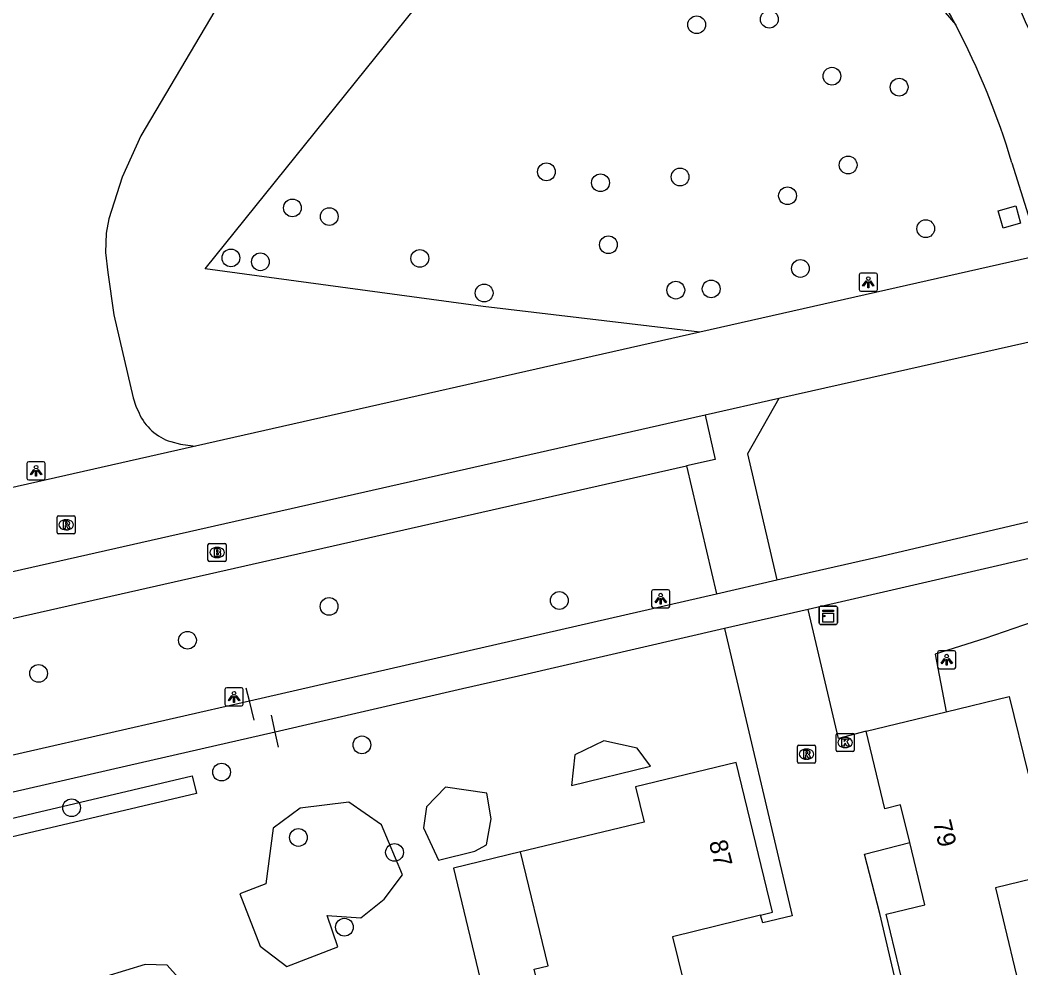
# Model space of a CAD drawing. Extents: x 156664 to 157568, y 383571 to 384421.
# Drawn here: x 156904.7 to 156959.8, y 384078.5 to 384130.7 of the extents above; entities that cross this region are included whole.
import ezdxf

# ---------------------------------------------------------------- set-up
doc = ezdxf.new("R2010")
doc.units = 0
for name, color, linetype in [('IMGEO_Boom', 7, 'Continuous'), ('IMGEO_Brandkraan', 7, 'Continuous'), ('IMGEO_Fietspad_gesloten', 7, 'Continuous'), ('IMGEO_Groenvoorziening', 7, 'Continuous'), ('IMGEO_Haag', 7, 'Continuous'), ('IMGEO_Hek', 7, 'Continuous'), ('IMGEO_Kast', 7, 'Continuous'), ('IMGEO_Kolk', 7, 'Continuous'), ('IMGEO_Lichtpunt', 7, 'Continuous'), ('IMGEO_Muur', 7, 'Continuous'), ('IMGEO_Naaldbos', 7, 'Continuous'), ('IMGEO_Pand', 7, 'Continuous'), ('IMGEO_Pand_nummerreeks', 7, 'Continuous'), ('IMGEO_Parkeervlak_open', 7, 'Continuous'), ('IMGEO_Rijbaan_lokaal_open', 7, 'Continuous'), ('IMGEO_Rioolput', 7, 'Continuous'), ('IMGEO_Voetpad_open', 7, 'Continuous')]:
    doc.layers.add(name, color=color, linetype=linetype)

msp = doc.modelspace()

# ---------------------------------------------------------------- linework, layer by layer
at = {"layer": 'IMGEO_Boom'}
for centre in [(156945.945, 384130.737), (156941.942, 384130.43), (156949.395, 384127.597), (156953.096, 384126.993), (156950.286, 384122.704), (156933.666, 384122.329), (156941.029, 384122.045), (156936.647, 384121.727), (156946.949, 384121.011), (156919.677, 384120.341), (156921.708, 384119.863), (156954.56, 384119.196), (156937.082, 384118.311), (156916.287, 384117.587), (156926.695, 384117.561), (156917.912, 384117.371), (156947.656, 384117.004), (156940.795, 384115.811), (156942.743, 384115.877), (156930.237, 384115.653), (156934.38, 384098.711), (156921.698, 384098.385), (156913.896, 384096.519), (156905.696, 384094.696), (156923.503, 384090.758), (156915.776, 384089.259), (156907.514, 384087.295), (156920.007, 384085.655), (156925.302, 384084.834), (156922.54, 384080.713)]:
    msp.add_circle(centre, 0.489, dxfattribs=at)
at = {"layer": 'IMGEO_Brandkraan'}
for p, q in [((156915.026, 384100.931), (156915.026, 384101.783)), ((156915.101, 384101.857), (156915.953, 384101.857)), ((156915.514, 384101.637), (156915.539, 384101.637)), ((156916.027, 384101.783), (156916.027, 384100.931)), ((156915.953, 384100.857), (156915.101, 384100.857)), ((156915.537, 384101.077), (156915.512, 384101.077))]:
    msp.add_line(p, q, dxfattribs=at)
for points in [[(156915.026, 384100.931), (156915.026, 384101.783)], [(156915.101, 384101.857), (156915.953, 384101.857)], [(156915.374, 384101.557), (156915.374, 384101.157), (156915.587, 384101.157)], [(156915.605, 384101.557), (156915.374, 384101.557)], [(156915.553, 384101.476), (156915.499, 384101.476), (156915.499, 384101.4)], [(156915.499, 384101.4), (156915.552, 384101.4)], [(156916.027, 384101.783), (156916.027, 384100.931)], [(156915.953, 384100.857), (156915.101, 384100.857)], [(156915.561, 384101.324), (156915.499, 384101.324), (156915.499, 384101.243)], [(156915.499, 384101.243), (156915.561, 384101.243)]]:
    msp.add_lwpolyline(points, dxfattribs=at)
for centre, radius, start, end in [((156915.103, 384101.781), 0.0765, 91.552, 178.448), ((156915.103, 384101.781), 0.0765, 91.552, 178.448), ((156915.554, 384101.438), 0.0379, 267.8285, 90.9355), ((156915.609, 384101.412), 0.145, 59.4692, 91.5367), ((156915.634, 384101.459), 0.0922, 285.5137, 58.1501), ((156915.951, 384101.781), 0.0765, 1.552, 88.448), ((156915.951, 384101.781), 0.0765, 1.552, 88.448), ((156915.103, 384100.933), 0.0765, 181.552, 268.448), ((156915.103, 384100.933), 0.0765, 181.552, 268.448), ((156915.562, 384101.283), 0.0404, 269.8759, 90.5077), ((156915.593, 384101.408), 0.251, 268.6676, 293.5347), ((156915.639, 384101.267), 0.105, 301.3115, 78.989), ((156915.951, 384100.933), 0.0765, 271.552, 358.448), ((156915.951, 384100.933), 0.0765, 271.552, 358.448)]:
    msp.add_arc(centre, radius, start, end, dxfattribs=at)
for centre, major_axis, ratio, start_param, end_param in [((156915.513, 384101.357), (-0.387, 0.002), 0.722429, 4.712389, 7.853982), ((156915.538, 384101.357), (-0.39, 0.002), 0.717154, 1.570796, 4.712389)]:
    msp.add_ellipse(centre, major_axis=major_axis, ratio=ratio, start_param=start_param, end_param=end_param, dxfattribs=at)
at = {"layer": 'IMGEO_Fietspad_gesloten'}
msp.add_lwpolyline([(156959.31, 384122.816), (156960.908, 384117.741)], dxfattribs=at)
for centre, radius, start, end in [((156917.342, 384110.12), 43.854, 27.5828, 32.8398), ((156914.405, 384109.729), 50.202, 20.2028, 27.9619), ((156917.613, 384110.277), 43.542, 16.7371, 27.565)]:
    msp.add_arc(centre, radius, start, end, dxfattribs=at)
at = {"layer": 'IMGEO_Groenvoorziening'}
for points in [[(156913.042, 384150.679), (156916.959, 384149.844), (156920.928, 384148.664), (156920.951, 384146.515), (156920.715, 384143.965), (156920.467, 384142.161), (156919.737, 384139.785), (156918.56, 384137.15), (156917.618, 384135.197), (156916.768, 384133.516), (156911.324, 384124.31), (156910.294, 384122.041), (156909.558, 384119.746), (156909.426, 384118.952), (156909.382, 384117.878), (156909.514, 384116.775), (156909.839, 384114.445), (156910.897, 384109.877), (156911.053, 384109.423), (156911.232, 384109.029)], [(156912.976, 384107.464), (156913.505, 384107.329), (156913.922, 384107.261), (156914.342, 384107.209)], [(156961.933, 384089.137), (156964.473, 384089.553), (156965.654, 384090.933), (156964.974, 384094.222), (156963.845, 384095.831), (156960.473, 384097.538), (156957.816, 384096.624), (156955.086, 384095.746), (156955.693, 384092.586)], [(156935.058, 384088.516), (156939.404, 384089.584), (156938.662, 384090.585), (156936.837, 384090.989), (156935.235, 384090.2), (156935.058, 384088.516)], [(156930.372, 384085.253), (156930.622, 384086.679), (156930.38, 384088.099), (156928.116, 384088.422), (156927.054, 384087.341), (156926.896, 384086.189), (156927.724, 384084.412), (156929.73, 384084.91), (156930.372, 384085.253)], [(156925.732, 384083.598), (156924.578, 384086.345), (156922.792, 384087.607), (156920.106, 384087.274), (156918.621, 384086.161), (156918.221, 384083.101), (156916.788, 384082.543), (156917.896, 384079.671), (156919.367, 384078.544), (156922.177, 384079.63), (156921.588, 384081.357), (156923.445, 384081.229), (156924.736, 384082.258), (156925.732, 384083.598)], [(156932.249, 384084.864), (156928.555, 384083.965), (156930.939, 384074.036)], [(156909.039, 384076.974), (156910.731, 384068.042), (156912.048, 384068.041), (156913.46, 384068.754), (156914.948, 384074.472), (156914.591, 384076.577), (156912.77, 384078.626), (156911.571, 384078.659), (156909.402, 384078), (156909.039, 384076.974)]]:
    msp.add_lwpolyline(points, dxfattribs=at)
msp.add_arc((156913.836, 384110.177), 2.846, 203.7829, 252.4099, dxfattribs=at)
at = {"layer": 'IMGEO_Haag'}
msp.add_lwpolyline([(156911.133, 384087.316), (156894.424, 384083.379), (156894.195, 384084.352), (156910.882, 384088.284), (156914.157, 384089.056), (156914.386, 384088.082), (156911.133, 384087.316)], dxfattribs=at)
at = {"layer": 'IMGEO_Hek'}
for points in [[(156917.305, 384093.191), (156917.132, 384093.888)], [(156917.57, 384092.125), (156917.305, 384093.191)], [(156918.727, 384091.464), (156918.524, 384092.403)], [(156918.907, 384090.628), (156918.727, 384091.464)]]:
    msp.add_lwpolyline(points, dxfattribs=at)
at = {"layer": 'IMGEO_Kast'}
for p, q in [((156948.694, 384097.468), (156948.694, 384098.309)), ((156948.694, 384098.309), (156948.694, 384097.468)), ((156948.769, 384098.393), (156949.61, 384098.393)), ((156949.61, 384098.393), (156948.769, 384098.393)), ((156949.694, 384098.318), (156949.694, 384097.477)), ((156949.694, 384097.477), (156949.694, 384098.318)), ((156949.619, 384097.393), (156948.778, 384097.393)), ((156948.778, 384097.393), (156949.619, 384097.393))]:
    msp.add_line(p, q, dxfattribs=at)
for points in [[(156948.889, 384098.183), (156949.489, 384098.183), (156949.489, 384098.098), (156948.889, 384098.098), (156948.889, 384098.183)], [(156948.889, 384098.008), (156949.489, 384098.008), (156949.489, 384097.519), (156948.889, 384097.519), (156948.889, 384098.008)]]:
    msp.add_lwpolyline(points, dxfattribs=at)
msp.add_circle((156948.973, 384097.857), 0.0377, dxfattribs=at)
for centre, start, end in [((156948.772, 384098.315), 92.4484, 184.2845), ((156948.772, 384098.315), 92.4484, 184.2845), ((156949.616, 384098.315), 2.4484, 94.2845), ((156949.616, 384098.315), 2.4484, 94.2845), ((156948.772, 384097.471), 182.4484, 274.2845), ((156948.772, 384097.471), 182.4484, 274.2845), ((156949.616, 384097.471), 272.4484, 4.2845), ((156949.616, 384097.471), 272.4484, 4.2845)]:
    msp.add_arc(centre, 0.0779, start, end, dxfattribs=at)
at = {"layer": 'IMGEO_Kolk'}
for p, q in [((156949.621, 384090.461), (156949.621, 384091.313)), ((156949.696, 384091.387), (156950.548, 384091.387)), ((156950.109, 384091.167), (156950.134, 384091.167)), ((156950.622, 384091.313), (156950.622, 384090.461)), ((156950.548, 384090.387), (156949.696, 384090.387)), ((156950.132, 384090.607), (156950.107, 384090.607))]:
    msp.add_line(p, q, dxfattribs=at)
for points in [[(156949.621, 384090.461), (156949.621, 384091.313)], [(156949.696, 384091.387), (156950.548, 384091.387)], [(156949.942, 384091.087), (156950.065, 384091.087), (156950.065, 384090.936), (156950.195, 384091.087), (156950.359, 384091.087), (156950.213, 384090.936), (156950.366, 384090.687), (156950.214, 384090.687), (156950.129, 384090.851), (156950.065, 384090.784), (156950.065, 384090.687), (156949.942, 384090.687), (156949.942, 384091.087)], [(156950.622, 384091.313), (156950.622, 384090.461)], [(156950.548, 384090.387), (156949.696, 384090.387)]]:
    msp.add_lwpolyline(points, dxfattribs=at)
for centre, start, end in [((156949.698, 384091.311), 91.552, 178.448), ((156949.698, 384091.311), 91.552, 178.448), ((156950.546, 384091.311), 1.552, 88.448), ((156950.546, 384091.311), 1.552, 88.448), ((156949.698, 384090.463), 181.552, 268.448), ((156949.698, 384090.463), 181.552, 268.448), ((156950.546, 384090.463), 271.552, 358.448), ((156950.546, 384090.463), 271.552, 358.448)]:
    msp.add_arc(centre, 0.0765, start, end, dxfattribs=at)
for centre, major_axis, ratio, start_param, end_param in [((156950.108, 384090.887), (-0.387, 0.002), 0.722429, 4.712389, 7.853982), ((156950.133, 384090.887), (-0.39, 0.002), 0.717154, 1.570796, 4.712389)]:
    msp.add_ellipse(centre, major_axis=major_axis, ratio=ratio, start_param=start_param, end_param=end_param, dxfattribs=at)
at = {"layer": 'IMGEO_Lichtpunt'}
for p, q in [((156950.9, 384116.652), (156950.9, 384115.845)), ((156950.9, 384116.652), (156950.9, 384115.845)), ((156951.802, 384116.747), (156950.994, 384116.747)), ((156951.802, 384116.747), (156950.994, 384116.747)), ((156951.896, 384115.845), (156951.896, 384116.652)), ((156951.896, 384115.845), (156951.896, 384116.652)), ((156950.994, 384115.751), (156951.802, 384115.751)), ((156950.994, 384115.751), (156951.802, 384115.751)), ((156905.057, 384106.26), (156905.057, 384105.453)), ((156905.057, 384106.26), (156905.057, 384105.453)), ((156905.959, 384106.355), (156905.151, 384106.355)), ((156905.959, 384106.355), (156905.151, 384106.355)), ((156906.053, 384105.453), (156906.053, 384106.26)), ((156906.053, 384105.453), (156906.053, 384106.26)), ((156905.151, 384105.359), (156905.959, 384105.359)), ((156905.151, 384105.359), (156905.959, 384105.359)), ((156939.464, 384099.212), (156939.464, 384098.405)), ((156939.464, 384099.212), (156939.464, 384098.405)), ((156940.366, 384099.307), (156939.558, 384099.307)), ((156940.366, 384099.307), (156939.558, 384099.307)), ((156940.46, 384098.405), (156940.46, 384099.212)), ((156940.46, 384098.405), (156940.46, 384099.212)), ((156939.558, 384098.311), (156940.366, 384098.311)), ((156939.558, 384098.311), (156940.366, 384098.311)), ((156956.119, 384095.945), (156955.311, 384095.945)), ((156956.119, 384095.945), (156955.311, 384095.945)), ((156955.217, 384095.85), (156955.217, 384095.043)), ((156955.217, 384095.85), (156955.217, 384095.043)), ((156956.213, 384095.043), (156956.213, 384095.85)), ((156956.213, 384095.043), (156956.213, 384095.85)), ((156955.311, 384094.949), (156956.119, 384094.949)), ((156955.311, 384094.949), (156956.119, 384094.949)), ((156915.963, 384093.806), (156915.963, 384092.999)), ((156915.963, 384093.806), (156915.963, 384092.999)), ((156916.865, 384093.901), (156916.057, 384093.901)), ((156916.865, 384093.901), (156916.057, 384093.901)), ((156916.959, 384092.999), (156916.959, 384093.806)), ((156916.959, 384092.999), (156916.959, 384093.806)), ((156916.057, 384092.905), (156916.865, 384092.905)), ((156916.057, 384092.905), (156916.865, 384092.905))]:
    msp.add_line(p, q, dxfattribs=at)
for points in [[(156951.274, 384116.316), (156951.313, 384116.288), (156951.125, 384116.026), (156951.087, 384116.053), (156951.274, 384116.316)], [(156951.486, 384116.288), (156951.524, 384116.315), (156951.711, 384116.053), (156951.672, 384116.025), (156951.486, 384116.288)], [(156951.376, 384116.268), (156951.423, 384116.268), (156951.423, 384115.946), (156951.376, 384115.946), (156951.376, 384116.268)], [(156905.431, 384105.924), (156905.47, 384105.896), (156905.282, 384105.634), (156905.244, 384105.661), (156905.431, 384105.924)], [(156905.533, 384105.876), (156905.58, 384105.876), (156905.58, 384105.554), (156905.533, 384105.554), (156905.533, 384105.876)], [(156905.643, 384105.896), (156905.681, 384105.923), (156905.868, 384105.661), (156905.829, 384105.633), (156905.643, 384105.896)], [(156939.838, 384098.876), (156939.877, 384098.848), (156939.689, 384098.586), (156939.651, 384098.613), (156939.838, 384098.876)], [(156939.94, 384098.828), (156939.987, 384098.828), (156939.987, 384098.506), (156939.94, 384098.506), (156939.94, 384098.828)], [(156940.05, 384098.848), (156940.088, 384098.875), (156940.275, 384098.613), (156940.236, 384098.585), (156940.05, 384098.848)], [(156955.591, 384095.514), (156955.63, 384095.486), (156955.442, 384095.224), (156955.404, 384095.251), (156955.591, 384095.514)], [(156955.693, 384095.466), (156955.74, 384095.466), (156955.74, 384095.144), (156955.693, 384095.144), (156955.693, 384095.466)], [(156955.803, 384095.486), (156955.841, 384095.513), (156956.028, 384095.251), (156955.989, 384095.223), (156955.803, 384095.486)], [(156916.337, 384093.47), (156916.376, 384093.442), (156916.188, 384093.18), (156916.15, 384093.207), (156916.337, 384093.47)], [(156916.439, 384093.422), (156916.486, 384093.422), (156916.486, 384093.1), (156916.439, 384093.1), (156916.439, 384093.422)], [(156916.549, 384093.442), (156916.587, 384093.469), (156916.774, 384093.207), (156916.735, 384093.179), (156916.549, 384093.442)]]:
    msp.add_lwpolyline(points, dxfattribs=at)
for centre in [(156951.399, 384116.45), (156905.556, 384106.058), (156939.963, 384099.01), (156955.716, 384095.648), (156916.462, 384093.604)]:
    msp.add_circle(centre, 0.0994, dxfattribs=at)
for centre, start, end in [((156950.994, 384116.652), 90, 180), ((156950.994, 384116.652), 90, 180), ((156951.802, 384116.652), 0, 90), ((156951.802, 384116.652), 0, 90), ((156950.994, 384115.845), 180, 270), ((156950.994, 384115.845), 180, 270), ((156951.802, 384115.845), 270, 0), ((156951.802, 384115.845), 270, 360), ((156905.151, 384106.26), 90, 180), ((156905.151, 384106.26), 90, 180), ((156905.959, 384106.26), 0, 90), ((156905.959, 384106.26), 0, 90), ((156905.151, 384105.453), 180, 270), ((156905.151, 384105.453), 180, 270), ((156905.959, 384105.453), 270, 0), ((156905.959, 384105.453), 270, 360), ((156939.558, 384099.212), 90, 180), ((156939.558, 384099.212), 90, 180), ((156940.366, 384099.212), 0, 90), ((156940.366, 384099.212), 0, 90), ((156939.558, 384098.405), 180, 270), ((156939.558, 384098.405), 180, 270), ((156940.366, 384098.405), 270, 0), ((156940.366, 384098.405), 270, 360), ((156955.311, 384095.85), 90, 180), ((156955.311, 384095.85), 90, 180), ((156956.119, 384095.85), 0, 90), ((156956.119, 384095.85), 0, 90), ((156955.311, 384095.043), 180, 270), ((156955.311, 384095.043), 180, 270), ((156956.119, 384095.043), 270, 0), ((156956.119, 384095.043), 270, 360), ((156916.057, 384093.806), 90, 180), ((156916.057, 384093.806), 90, 180), ((156916.865, 384093.806), 0, 90), ((156916.865, 384093.806), 0, 90), ((156916.057, 384092.999), 180, 270), ((156916.057, 384092.999), 180, 270), ((156916.865, 384092.999), 270, 0), ((156916.865, 384092.999), 270, 360)]:
    msp.add_arc(centre, 0.0946, start, end, dxfattribs=at)
at = {"layer": 'IMGEO_Muur'}
msp.add_lwpolyline([(156958.817, 384119.224), (156958.548, 384120.185), (156959.515, 384120.455), (156959.784, 384119.495), (156958.817, 384119.224)], dxfattribs=at)
at = {"layer": 'IMGEO_Naaldbos'}
msp.add_lwpolyline([(156942.127, 384113.492), (156930.191, 384114.906), (156914.869, 384116.99), (156927.02, 384132.097), (156927.884, 384140.558), (156926.305, 384149.362), (156933.269, 384157.022), (156956.212, 384130.426)], dxfattribs=at)
at = {"layer": 'IMGEO_Pand'}
for points in [[(156955.693, 384092.586), (156959.161, 384093.426), (156960.202, 384089.155), (156961.833, 384089.551), (156961.933, 384089.137)], [(156951.271, 384091.515), (156955.693, 384092.586)], [(156953.681, 384085.38), (156953.179, 384087.448), (156952.313, 384087.237), (156951.271, 384091.515)], [(156945.461, 384081.373), (156946.117, 384081.533), (156944.115, 384089.783), (156938.568, 384088.437), (156939.043, 384086.504), (156932.249, 384084.864)], [(156933.906, 384074.537), (156932.99, 384078.392), (156933.768, 384078.586), (156932.249, 384084.864)], [(156954.047, 384074.482), (156952.377, 384081.427), (156954.516, 384081.941), (156953.681, 384085.38)], [(156963.163, 384084.034), (156958.41, 384082.88), (156960.083, 384075.91)], [(156945.461, 384081.373), (156940.609, 384080.187), (156941.558, 384076.308), (156940.57, 384076.066)]]:
    msp.add_lwpolyline(points, dxfattribs=at)
at = {"layer": 'IMGEO_Parkeervlak_open'}
msp.add_lwpolyline([(156891.161, 384094.76), (156941.38, 384106.125)], dxfattribs=at)
at = {"layer": 'IMGEO_Rijbaan_lokaal_open'}
for points in [[(156960.908, 384117.741), (156942.127, 384113.492)], [(156963.43, 384113.691), (156962.062, 384113.35), (156950.799, 384110.819), (156946.471, 384109.84)], [(156942.127, 384113.492), (156914.342, 384107.209)], [(156946.471, 384109.84), (156942.411, 384108.921)], [(156946.471, 384109.84), (156944.735, 384106.798), (156946.364, 384099.845)], [(156942.411, 384108.921), (156892.56, 384097.639)], [(156942.411, 384108.921), (156942.963, 384106.483), (156941.38, 384106.125)], [(156914.342, 384107.209), (156854.008, 384093.566)], [(156941.38, 384106.125), (156943.045, 384099.085)], [(156943.045, 384099.085), (156946.364, 384099.845)], [(156948.077, 384098.217), (156943.484, 384097.16)], [(156951.271, 384091.515), (156949.765, 384091.101), (156948.077, 384098.217)], [(156943.484, 384097.16), (156947.199, 384081.344), (156945.581, 384080.944), (156945.461, 384081.373)], [(156954.047, 384074.482), (156953.688, 384074.389), (156952.038, 384081.474), (156951.183, 384084.738), (156953.681, 384085.38)]]:
    msp.add_lwpolyline(points, dxfattribs=at)
at = {"layer": 'IMGEO_Rioolput'}
for p, q in [((156906.713, 384102.458), (156906.713, 384103.31)), ((156906.788, 384103.384), (156907.64, 384103.384)), ((156907.201, 384103.164), (156907.226, 384103.164)), ((156907.714, 384103.31), (156907.714, 384102.458)), ((156907.224, 384102.604), (156907.199, 384102.604)), ((156907.64, 384102.384), (156906.788, 384102.384)), ((156947.496, 384089.821), (156947.496, 384090.673)), ((156947.571, 384090.747), (156948.423, 384090.747)), ((156947.984, 384090.527), (156948.009, 384090.527)), ((156948.497, 384090.673), (156948.497, 384089.821)), ((156948.007, 384089.967), (156947.982, 384089.967)), ((156948.423, 384089.747), (156947.571, 384089.747))]:
    msp.add_line(p, q, dxfattribs=at)
for points in [[(156906.713, 384102.458), (156906.713, 384103.31)], [(156906.788, 384103.384), (156907.64, 384103.384)], [(156907.302, 384103.082), (156907.05, 384103.084), (156907.05, 384102.684)], [(156907.714, 384103.31), (156907.714, 384102.458)], [(156907.05, 384102.684), (156907.174, 384102.684), (156907.174, 384102.846), (156907.185, 384102.846)], [(156907.228, 384103.003), (156907.174, 384103.003), (156907.174, 384102.922)], [(156907.174, 384102.922), (156907.226, 384102.922)], [(156907.232, 384102.817), (156907.303, 384102.684), (156907.443, 384102.684), (156907.378, 384102.81)], [(156907.64, 384102.384), (156906.788, 384102.384)], [(156947.496, 384089.821), (156947.496, 384090.673)], [(156947.571, 384090.747), (156948.423, 384090.747)], [(156948.085, 384090.445), (156947.833, 384090.447), (156947.833, 384090.047)], [(156948.497, 384090.673), (156948.497, 384089.821)], [(156947.833, 384090.047), (156947.957, 384090.047), (156947.957, 384090.209), (156947.968, 384090.209)], [(156948.011, 384090.366), (156947.957, 384090.366), (156947.957, 384090.285)], [(156947.957, 384090.285), (156948.009, 384090.285)], [(156948.015, 384090.18), (156948.086, 384090.047), (156948.226, 384090.047), (156948.161, 384090.173)], [(156948.423, 384089.747), (156947.571, 384089.747)]]:
    msp.add_lwpolyline(points, dxfattribs=at)
for centre, radius, start, end in [((156906.79, 384103.308), 0.0765, 91.552, 178.448), ((156906.79, 384103.308), 0.0765, 91.552, 178.448), ((156907.301, 384102.972), 0.109, 350.3612, 89.416), ((156907.638, 384103.308), 0.0765, 1.552, 88.448), ((156907.638, 384103.308), 0.0765, 1.552, 88.448), ((156907.184, 384102.793), 0.0533, 26.0293, 88.6989), ((156907.21, 384103.111), 0.19, 274.7715, 282.9687), ((156907.234, 384102.907), 0.0964, 77.0061, 93.1865), ((156907.248, 384102.964), 0.0378, 276.6634, 79.6772), ((156907.299, 384102.972), 0.112, 277.5842, 350.9817), ((156907.283, 384102.757), 0.108, 29.5134, 73.7905), ((156906.79, 384102.46), 0.0765, 181.552, 268.448), ((156906.79, 384102.46), 0.0765, 181.552, 268.448), ((156907.638, 384102.46), 0.0765, 271.552, 358.448), ((156907.638, 384102.46), 0.0765, 271.552, 358.448), ((156947.573, 384090.671), 0.0765, 91.552, 178.448), ((156947.573, 384090.671), 0.0765, 91.552, 178.448), ((156948.084, 384090.335), 0.109, 350.3612, 89.416), ((156948.421, 384090.671), 0.0765, 1.552, 88.448), ((156948.421, 384090.671), 0.0765, 1.552, 88.448), ((156947.573, 384089.823), 0.0765, 181.552, 268.448), ((156947.573, 384089.823), 0.0765, 181.552, 268.448), ((156947.967, 384090.156), 0.0533, 26.0293, 88.6989), ((156947.993, 384090.474), 0.19, 274.7715, 282.9687), ((156948.017, 384090.27), 0.0964, 77.0061, 93.1865), ((156948.031, 384090.327), 0.0378, 276.6634, 79.6772), ((156948.082, 384090.335), 0.112, 277.5842, 350.9817), ((156948.066, 384090.12), 0.108, 29.5134, 73.7905), ((156948.421, 384089.823), 0.0765, 271.552, 358.448), ((156948.421, 384089.823), 0.0765, 271.552, 358.448)]:
    msp.add_arc(centre, radius, start, end, dxfattribs=at)
for centre, major_axis, ratio, start_param, end_param in [((156907.2, 384102.884), (-0.387, 0.002), 0.722429, 4.712389, 7.853982), ((156907.225, 384102.884), (-0.39, 0.002), 0.717154, 1.570796, 4.712389), ((156947.983, 384090.247), (-0.387, 0.002), 0.722429, 4.712389, 7.853982), ((156948.008, 384090.247), (-0.39, 0.002), 0.717154, 1.570796, 4.712389)]:
    msp.add_ellipse(centre, major_axis=major_axis, ratio=ratio, start_param=start_param, end_param=end_param, dxfattribs=at)
at = {"layer": 'IMGEO_Voetpad_open'}
for points in [[(156946.364, 384099.845), (156951.863, 384101.104), (156964.167, 384103.981), (156970.736, 384105.485)], [(156972.714, 384103.756), (156964.624, 384102.037), (156953.435, 384099.449), (156948.077, 384098.217)], [(156896.269, 384092.742), (156897.184, 384088.584), (156917.305, 384093.191), (156943.045, 384099.085)], [(156943.484, 384097.16), (156932.125, 384094.547), (156929.047, 384093.838), (156918.727, 384091.464), (156910.543, 384089.588), (156893.311, 384085.637)]]:
    msp.add_lwpolyline(points, dxfattribs=at)

# ---------------------------------------------------------------- texts
at = {"layer": 'IMGEO_Pand_nummerreeks'}
for s, rotation, p in [('79', 283.6476, (156954.953, 384086.497)), ('87', 283.6419, (156942.608, 384085.394))]:
    msp.add_text(s, height=1, rotation=rotation, dxfattribs=at).set_placement(p)

doc.saveas('drawing.dxf')
